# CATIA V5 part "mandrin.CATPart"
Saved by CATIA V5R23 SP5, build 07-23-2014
Part number: mandrin
Definition: mandrin
Source: made
Bounding box of the stored display mesh (mm): x -2 to 106, y -37.452 to 37.452, z -37.5 to 37.5
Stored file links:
  C:\wamp\www\COURS\CONCEPTION GMP1\TITRE 01-CATIA VOLUMIQUE\05--ACTIONNEUR DE VANNE\prof\CORRECTION\Assemblage\mandrin.CATPart
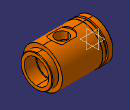
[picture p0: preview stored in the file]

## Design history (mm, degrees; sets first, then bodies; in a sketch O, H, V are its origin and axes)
Set1
  Point1: type Center, Curve edge [face of Solid1 | face of Solid1]
Body1 "NONE" (main body)
  Solid1 "Manifold Solid #1187": solid without history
